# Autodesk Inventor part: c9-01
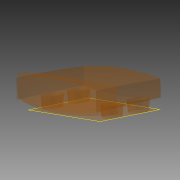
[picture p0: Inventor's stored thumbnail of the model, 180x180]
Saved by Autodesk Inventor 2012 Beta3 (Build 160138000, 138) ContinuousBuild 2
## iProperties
Created: 2010-12
Part Number: c9-01
Material: Default
Document SubType Name: Modeling
Designer: Beta-8540w
Density: 1 g/cm^3
Author: Beta-8540w
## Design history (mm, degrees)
sketch "Sketch1"
  geometry: L1 (-60, -12)-(60, -12); L2 (60, -12)-(60, 12); L3 (60, 12)-(-60, 12); L4 (-60, 12)-(-60, -12); A1 r 350 centre (0, -332.819) between (60, 12) and (-60, 12); A2 r 350 centre (0, 332.819) between (-60, -12) and (60, -12); 3 further points
  constraints: 8 end point, 4 point on circle, 2 centre point, 2 midpoint, 2 parallel, 1 equal radius, 1 horizontal, 1 horizontal alignment, 1 perpendicular, 1 vertical alignment
  dimensions: "d0" = 120 distance of L3.end L2.end; "d1" = 24 distance of L2.end L1.end; "d2" = 350 radius of A1
workplane "Work Plane4"
sketch "Sketch5"
  geometry: L1 (-60, 12)-(-60, -12) reference; L2 (60, -12)-(60, 12) reference; L3 (-58, 10.314)-(-58, -10.314); L4 (58, -10.314)-(58, 10.314); A1 r 350 centre (0, 332.819) between (-60, -12) and (60, -12) reference; A2 r 350 centre (0, -332.819) between (60, 12) and (-60, 12) reference; A3 r 348 centre (0, 332.819) between (-58, -10.314) and (58, -10.314); A4 r 348 centre (0, -332.819) between (58, 10.314) and (-58, 10.314); 1 further point
  constraints: 4 end point, 4 point on circle, 2 centre point, 3 other
  dimensions: "d37" = 2 distance between parallel lines of L2 L4
sketch "Sketch6"
  geometry: L1 (-60, 0)-(60, 0); L2 (60, 0)-(58.843, 22.085); L3 (-60, 0)-(-58.779, 23.307); A1 r 691.758 centre (630.81, -36.204) between (-60, 0) and (-58, -100); A2 r 691.758 centre (-630.81, -36.204) between (58, -100) and (60, 0); 1 further point
  constraints: 6 end point, 4 point on circle, 2 centre point, 2 tangent, 1 horizontal
  dimensions: "d53" = 87 deg angle of L1 L3; "d54" = 87 deg angle of L1 L2 (= d53)
sketch "Sketch7"
  geometry: L1 (17.181, 0)-(12, 0) reference; L2 (15.181, -100)-(10.314, -100) reference; L3 (17.181, 0)-(16.768, 11.838); A1 r 911.322 centre (-893.585, -31.805) between (15.181, -100) and (17.181, 0); 1 further point
  constraints: 2 end point, 2 point on circle, 1 centre point, 1 tangent
  dimensions: "d56" = 88 deg angle of L1 L3
feature "LoftSrf2" sketch "Sketch5", "Sketch6", "Sketch7" dims "d57" = 0, "d58" = 90 deg, "d59" = 0, "d60" = 90 deg, "d61" = 0, "d62" = 90 deg, "d63" = 0, "d64" = 90 deg, "d65" = 0, "d66" = 90 deg
sketch "Sketch2"
  geometry: L1 (-75, -16)-(75, -16); L2 (-75, -60)-(75, -60); A1 r 183.781 centre (0, -183.781) between (75, -16) and (-75, -16); 2 further points
  constraints: 4 end point, 3 point on circle, 1 centre point, 1 coincident, 1 horizontal, 1 parallel
  dimensions: "d5" = 16 distance from line of point (0, 0) L1; "d7" = 60 distance from line of point (0, 0) L2; "d55" = 150 distance of L1.start L1.end
feature "RevolutionSrf1" sketch "Sketch2" dims angle "d8" = 40 deg
patch "Boundary Patch1" dims "d13" = 0, "d67" = 0, "d68" = 0, "d69" = 0, "d70" = 0
workplane "Work Plane1"
sketch "Sketch3"
  geometry: L1 (52, -85)-(52, -73); L2 (38, -73)-(38, -85); A1 r 7 centre (45, -73) between (52, -73) and (38, -73); A2 r 7 centre (45, -85) between (38, -85) and (52, -85); 1 further point
  constraints: 4 end point, 4 point on circle, 4 tangent, 2 centre point, 1 parallel, 1 vertical
  dimensions: "d15" = 12 distance of L1.start L1.end; "d16" = 7 radius of A1; "d50" = 45 horizontal distance of A1.centre point (0, 0); "d51" = 85 vertical distance of point (0, 0) A2.centre
extrude_surface "ExtrusionSrf2" sketch "Sketch3" dims "d19" = 14, "d20" = 5 deg
pattern_linear "Rectangular Pattern1" dims "d23" = 90
workplane "Work Plane2"
body "Srf2"
body "Srf3"
body "Srf4"
body "Srf5"
body "Srf6"
body "Srf7"
body "Srf11"
extrude_surface "ExtrusionSrf3"
extrude_surface "ExtrusionSrf4"
extrude_surface "ExtrusionSrf5"
other parameters: "d14" = -24, "d52" = -6
